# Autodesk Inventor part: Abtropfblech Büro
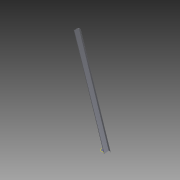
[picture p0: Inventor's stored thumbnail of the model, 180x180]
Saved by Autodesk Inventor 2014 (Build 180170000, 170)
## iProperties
Created: 2013-09
Part Number: Abtropfblech Büro
Material: Aluminium 6061
Document SubType Name: Modeling
Designer: Stefan Tammegger
Mass: 2632.18 g
Surface Area: 13058.9 cm^2
Volume: 971.285 cm^3
Density: 2.71 g/cm^3
Appearance: Aluminium - flach
Author: Stefan Tammegger
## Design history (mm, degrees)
workplane "Arbeitsebene2"
sketch "Skizze1"
  geometry: L1 (85.448, 1024.58)-(64.301, 21.843) reference; L2 (1001.875, -57.712)-(-2689.836, -57.189) reference; L3 (82, -28)-(82, 28) reference; L4 (80, 30)-(67, 30) reference; L5 (147, -57.591)-(157.607, -46.984); L6 (147, -57.591)-(162, -57.591); L7 (147, -57.591)-(97, -57.584); L8 (97, -57.584)-(87.428, 51.999); L9 (87.428, 51.999)-(72.428, 52.001); L10 (72.429, 53.501)-(88.803, 53.499); L11 (88.803, 53.499)-(98.375, -56.084); L12 (98.375, -56.084)-(146.379, -56.091); L13 (146.379, -56.091)-(156.546, -45.924); L14 (156.546, -45.924)-(157.607, -46.984); L15 (72.429, 53.501)-(72.428, 52.001); 1 further point
  constraints: 22 end point, 3 parallel, 2 perpendicular, 2 point on line, 1 equal length, 1 horizontal, 1 other
  dimensions: "d0" = 15 distance of L5.start L5.end; "d1" = 45 deg angle of L6 L5; "d2" = 50 distance of L5.start L7.end; "d3" = 110 distance of L7.end L8.end; "d4" = 95 deg angle of L7 L8; "d5" = 15 distance of L8.end L9.end; "d6" = 1.5 distance between parallel lines of L11 L8; "d7" = 1.5 distance between parallel lines of L9 L10 (derived); "d8" = 1.5 distance between parallel lines of L5 L13; "d9" = 1.5 distance between parallel lines of L2 L12; "d10" = 15 distance from line of L7.end L3
  node "Referenz1"
  node "Referenz2"
  node "Referenz3"
  node "Referenz4"
workplane "Arbeitsebene3"
extrude "Extrusion1" new body sketch "Skizze1" stored distance "d11" = 10; taper "d12" = 0 deg
node "Volumenkörper1"
